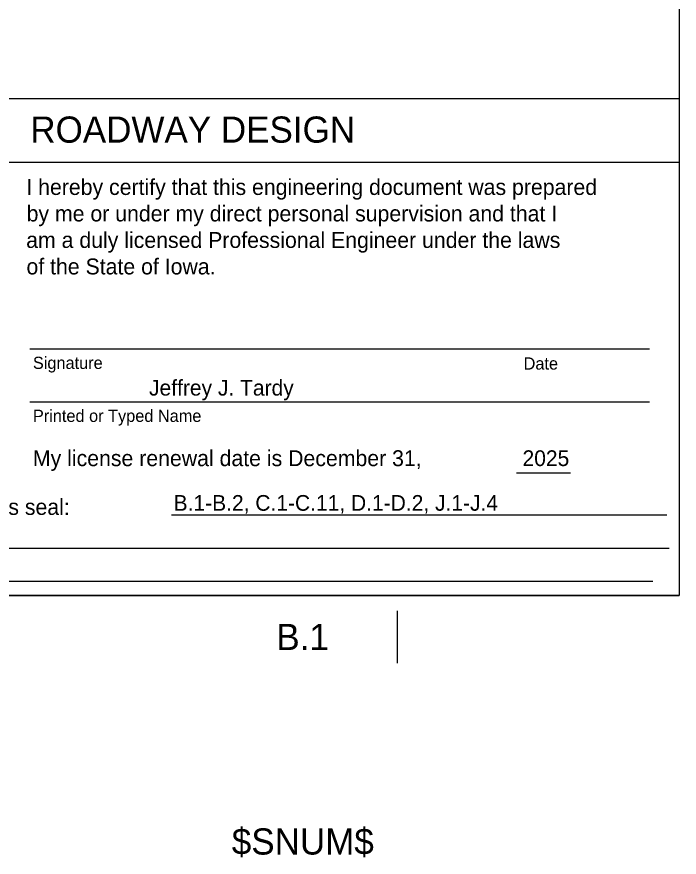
# Model space of a CAD drawing. Extents: x -2096698 to 6160, y -2144490 to 6200.
# Drawn here: x 5625 to 6132, y 4009 to 4651 of the extents above; entities that cross this region are included whole.
import ezdxf

# ---------------------------------------------------------------- set-up
doc = ezdxf.new("R2010")
doc.units = 0
for name, color, linetype in [('DsnShtInsideBorder', 7, 'Continuous'), ('dsnTextCpn', 7, 'Continuous'), ('Level 15', 7, 'Continuous'), ('Level 2', 7, 'Continuous'), ('Level 3', 7, 'Continuous')]:
    doc.layers.add(name, color=color, linetype=linetype)

msp = doc.modelspace()

# ---------------------------------------------------------------- linework, layer by layer
at = {"layer": 'DsnShtInsideBorder'}
msp.add_line((5916.11, 4197.2), (5916.11, 4157.2), dxfattribs=at)
at = {"layer": 'Level 15'}
for p in [(6131.53, 5293.41), (3074.9, 4208.97)]:
    msp.add_line(p, (6131.53, 4208.97), dxfattribs=at)
at = {"layer": 'Level 2'}
for p, q in [((5375.6, 4540.02), (6131.53, 4540.02)), ((6108.96, 4397.04), (5635.24, 4397.04)), ((6108.96, 4356.55), (5635.24, 4356.55)), ((6048.47, 4302.36), (6007.11, 4302.36)), ((5743.49, 4270.49), (6122.18, 4270.49)), ((5382.93, 4245.18), (6123.89, 4245.18)), ((5395.82, 4219.87), (6111.37, 4219.87))]:
    msp.add_line(p, q, dxfattribs=at)
msp.add_lwpolyline([(5375.6, 4588.62), (6131.53, 4588.62), (6131.53, 4208.97), (5375.6, 4208.97)], close=True, dxfattribs=at)

# ---------------------------------------------------------------- texts
at = {"layer": 'dsnTextCpn'}
msp.add_text('$SNUM$', height=20, dxfattribs=at).set_placement((5789.66, 4010.91))
at = {"layer": 'Level 2'}
msp.add_text('ROADWAY DESIGN', height=20, dxfattribs=at).set_placement((5635.68, 4554.96))
for s, height, p in [('I hereby certify that this engineering document was prepared', 12.1488, (5632.63, 4515)), ('by me or under my direct personal supervision and that I', 12.1488, (5632.85, 4494.75)), ('am a duly licensed Professional Engineer under the laws', 12.1488, (5632.52, 4474.51)), ('of the State of Iowa.', 12.1488, (5632.73, 4454.26)), ('Signature', 9.314, (5637.65, 4382.05)), ('Date', 9.314, (6012.64, 4381.54)), ('Jeffrey J. Tardy', 12, (5726.4, 4361.66)), ('Printed or Typed Name', 9.3141, (5637.65, 4341.56)), ('My license renewal date is December 31,', 12.1488, (5637.65, 4307.74)), ('2025', 12, (6011.82, 4307.82)), ('B.1-B.2, C.1-C.11, D.1-D.2, J.1-J.4', 12, (5745.18, 4273.65)), ('Pages or sheets covered by this seal:', 12.1488, (5395.82, 4270.49))]:
    msp.add_text(s, height=height, rotation=0, dxfattribs=at).set_placement(p)
at = {"layer": 'Level 3'}
msp.add_text('B.1', height=20, dxfattribs=at).set_placement((5823.69, 4167.2))

doc.saveas('drawing.dxf')
